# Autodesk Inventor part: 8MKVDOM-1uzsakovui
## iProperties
Created: 2009-08
Part Number: 8MKVDOM-1uzsakovui
Document SubType Name: Modeling
Designer: Darius
Author: Darius
Translation Standard: STEP AP203
File Name: 8MKVDOM-1.STEP
Preprocessor: SolidWorks 2003240
Postprocessor: Build: 272, Release: 10 SP3a - Date: Thu 12/15/2005
Sent Units: MILLIMETERS
Uncertainty: 1e-05
